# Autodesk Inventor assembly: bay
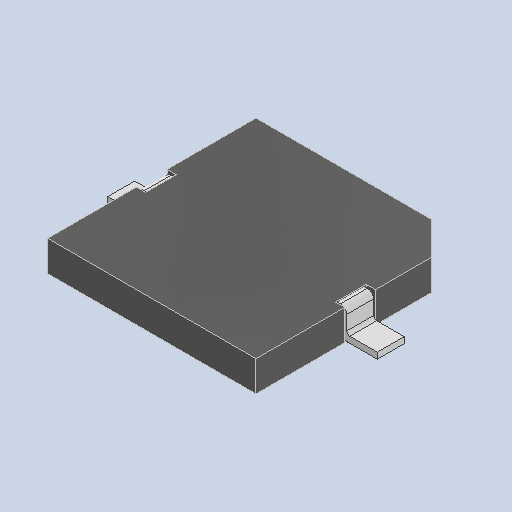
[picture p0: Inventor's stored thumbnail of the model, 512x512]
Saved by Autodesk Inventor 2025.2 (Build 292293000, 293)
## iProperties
Created: 2025-04
Part Number: bay
Description: PART--DESC
Document SubType Name: Assembly
Designer: BennF
Author: BennF
Revision Number: NONE
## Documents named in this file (3)
- C:\Users\BennF\Nextcloud\Benutzer\CNC JarBeRi\existing parts\Electronics\RepRap A4988 Shied (USE WITHOUT ARDUINO)\reprap-a4988-1.snapshot.1\RepRap\RepRap\bay_3.iam
- C:\Users\BennF\Nextcloud\Benutzer\CNC JarBeRi\existing parts\Electronics\RepRap A4988 Shied (USE WITHOUT ARDUINO)\reprap-a4988-1.snapshot.1\RepRap\RepRap\bay Geometry.ipt
- C:\Users\BennF\Nextcloud\Benutzer\CNC JarBeRi\existing parts\Electronics\RepRap A4988 Shied (USE WITHOUT ARDUINO)\reprap-a4988-1.snapshot.1\RepRap\RepRap\pin14.ipt
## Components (2 placed, 2 different names)
1. bay Geometry
2. pin14
